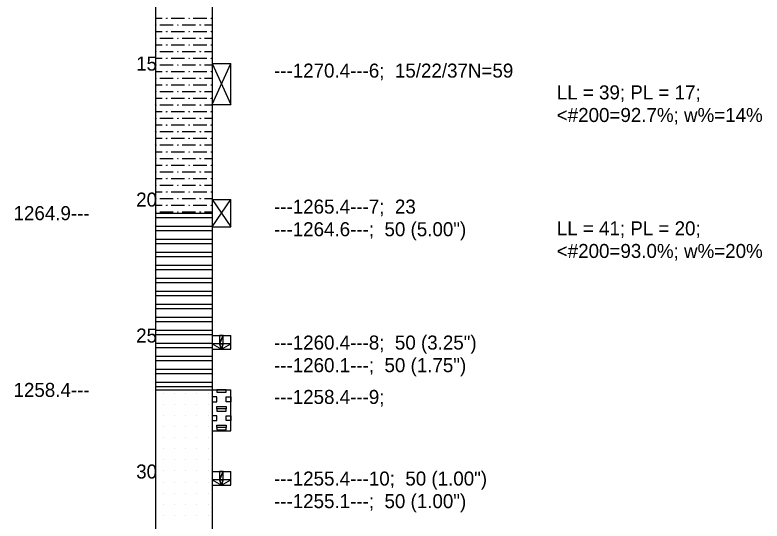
# Model space of a CAD drawing. Extents: x 2150148.6 to 2150220.1, y 143803.7 to 143875.1.
# Drawn here: x 2150175.11 to 2150181.72, y 143820.24 to 143824.71 of the extents above; entities that cross this region are included whole.
import ezdxf

# ---------------------------------------------------------------- set-up
doc = ezdxf.new("R2010")
doc.units = 0
doc.layers.add('Default', color=7, linetype='Continuous')

# ---------------------------------------------------------------- blocks, each defined once
blk = doc.blocks.new('POINT_DISPLAY')
at = {"layer": 'Default'}
blk.add_line((0, 0), (0, 0), dxfattribs=at)

msp = doc.modelspace()

# ---------------------------------------------------------------- linework, layer by layer
at = {"layer": 'Default'}
for points in [[(2150176.3564, 143827.8881), (2150176.3564, 143815.8689)], [(2150176.8564, 143827.8881), (2150176.8564, 143815.8689)], [(2150176.3564, 143824.6849), (2150176.4154, 143824.6849)], [(2150176.4548, 143824.6849), (2150176.4587, 143824.6849), (2150176.4548, 143824.681), (2150176.4548, 143824.6849)], [(2150176.4942, 143824.6849), (2150176.6123, 143824.6849)], [(2150176.6516, 143824.6849), (2150176.6556, 143824.6849), (2150176.6556, 143824.681), (2150176.6516, 143824.6849)], [(2150176.691, 143824.6849), (2150176.7501, 143824.6849)], [(2150176.7501, 143824.6849), (2150176.8091, 143824.6849)], [(2150176.8485, 143824.6849), (2150176.8524, 143824.6849), (2150176.8485, 143824.681), (2150176.8485, 143824.6849)], [(2150176.3564, 143824.6258), (2150176.3603, 143824.6258), (2150176.3603, 143824.6219), (2150176.3564, 143824.6258)], [(2150176.3957, 143824.6258), (2150176.5138, 143824.6258)], [(2150176.5532, 143824.6258), (2150176.5571, 143824.6258), (2150176.5532, 143824.6219), (2150176.5532, 143824.6258)], [(2150176.5926, 143824.6258), (2150176.7107, 143824.6258)], [(2150176.7501, 143824.6258), (2150176.754, 143824.6258), (2150176.754, 143824.6219), (2150176.7501, 143824.6258)], [(2150176.7894, 143824.6258), (2150176.8564, 143824.6258)], [(2150176.3564, 143824.5668), (2150176.4154, 143824.5668)], [(2150176.4548, 143824.5668), (2150176.4587, 143824.5668), (2150176.4548, 143824.5629), (2150176.4548, 143824.5668)], [(2150176.4942, 143824.5668), (2150176.6123, 143824.5668)], [(2150176.6516, 143824.5668), (2150176.6556, 143824.5668), (2150176.6556, 143824.5629), (2150176.6516, 143824.5668)], [(2150176.691, 143824.5668), (2150176.7501, 143824.5668)], [(2150176.7501, 143824.5668), (2150176.8091, 143824.5668)], [(2150176.8485, 143824.5668), (2150176.8524, 143824.5668), (2150176.8485, 143824.5629), (2150176.8485, 143824.5668)], [(2150176.3564, 143824.5077), (2150176.3603, 143824.5077), (2150176.3603, 143824.5038), (2150176.3564, 143824.5077)], [(2150176.3564, 143824.4487), (2150176.4154, 143824.4487)], [(2150176.3957, 143824.5077), (2150176.5138, 143824.5077)], [(2150176.4548, 143824.4487), (2150176.4587, 143824.4487), (2150176.4548, 143824.4447), (2150176.4548, 143824.4487)], [(2150176.4942, 143824.4487), (2150176.6123, 143824.4487)], [(2150176.5532, 143824.5077), (2150176.5571, 143824.5077), (2150176.5532, 143824.5038), (2150176.5532, 143824.5077)], [(2150176.5926, 143824.5077), (2150176.7107, 143824.5077)], [(2150176.6516, 143824.4487), (2150176.6556, 143824.4487), (2150176.6556, 143824.4447), (2150176.6516, 143824.4487)], [(2150176.691, 143824.4487), (2150176.7501, 143824.4487)], [(2150176.7501, 143824.5077), (2150176.754, 143824.5077), (2150176.754, 143824.5038), (2150176.7501, 143824.5077)], [(2150176.7501, 143824.4487), (2150176.8091, 143824.4487)], [(2150176.7894, 143824.5077), (2150176.8564, 143824.5077)], [(2150176.8485, 143824.4487), (2150176.8524, 143824.4487), (2150176.8485, 143824.4447), (2150176.8485, 143824.4487)], [(2150176.3564, 143824.3896), (2150176.3603, 143824.3896), (2150176.3603, 143824.3857), (2150176.3564, 143824.3896)], [(2150176.3957, 143824.3896), (2150176.5138, 143824.3896)], [(2150176.5532, 143824.3896), (2150176.5571, 143824.3896), (2150176.5532, 143824.3857), (2150176.5532, 143824.3896)], [(2150176.5926, 143824.3896), (2150176.7107, 143824.3896)], [(2150176.7501, 143824.3896), (2150176.754, 143824.3896), (2150176.754, 143824.3857), (2150176.7501, 143824.3896)], [(2150176.7894, 143824.3896), (2150176.8564, 143824.3896)], [(2150176.3564, 143824.3306), (2150176.4154, 143824.3306)], [(2150176.4548, 143824.3306), (2150176.4587, 143824.3306), (2150176.4548, 143824.3266), (2150176.4548, 143824.3306)], [(2150176.4942, 143824.3306), (2150176.6123, 143824.3306)], [(2150176.6516, 143824.3306), (2150176.6556, 143824.3306), (2150176.6556, 143824.3266), (2150176.6516, 143824.3306)], [(2150176.691, 143824.3306), (2150176.7501, 143824.3306)], [(2150176.7501, 143824.3306), (2150176.8091, 143824.3306)], [(2150176.8485, 143824.3306), (2150176.8524, 143824.3306), (2150176.8485, 143824.3266), (2150176.8485, 143824.3306)], [(2150176.3564, 143824.2715), (2150176.3603, 143824.2715), (2150176.3603, 143824.2676), (2150176.3564, 143824.2715)], [(2150176.3957, 143824.2715), (2150176.5138, 143824.2715)], [(2150176.5532, 143824.2715), (2150176.5571, 143824.2715), (2150176.5532, 143824.2676), (2150176.5532, 143824.2715)], [(2150176.5926, 143824.2715), (2150176.7107, 143824.2715)], [(2150176.7501, 143824.2715), (2150176.754, 143824.2715), (2150176.754, 143824.2676), (2150176.7501, 143824.2715)], [(2150176.7894, 143824.2715), (2150176.8564, 143824.2715)], [(2150176.8564, 143824.2823), (2150177.023, 143823.9217)], [(2150176.8564, 143823.9217), (2150177.023, 143824.2823)], [(2150176.8564, 143824.2823), (2150177.023, 143824.2823)], [(2150177.023, 143823.9217), (2150177.023, 143824.2823)], [(2150176.3564, 143824.2125), (2150176.4154, 143824.2125)], [(2150176.4548, 143824.2125), (2150176.4587, 143824.2125), (2150176.4548, 143824.2085), (2150176.4548, 143824.2125)], [(2150176.4942, 143824.2125), (2150176.6123, 143824.2125)], [(2150176.6516, 143824.2125), (2150176.6556, 143824.2125), (2150176.6556, 143824.2085), (2150176.6516, 143824.2125)], [(2150176.691, 143824.2125), (2150176.7501, 143824.2125)], [(2150176.7501, 143824.2125), (2150176.8091, 143824.2125)], [(2150176.8485, 143824.2125), (2150176.8524, 143824.2125), (2150176.8485, 143824.2085), (2150176.8485, 143824.2125)], [(2150176.3564, 143824.1534), (2150176.3603, 143824.1534), (2150176.3603, 143824.1495), (2150176.3564, 143824.1534)], [(2150176.3957, 143824.1534), (2150176.5138, 143824.1534)], [(2150176.5532, 143824.1534), (2150176.5571, 143824.1534), (2150176.5532, 143824.1495), (2150176.5532, 143824.1534)], [(2150176.5926, 143824.1534), (2150176.7107, 143824.1534)], [(2150176.7501, 143824.1534), (2150176.754, 143824.1534), (2150176.754, 143824.1495), (2150176.7501, 143824.1534)], [(2150176.7894, 143824.1534), (2150176.8564, 143824.1534)], [(2150176.3564, 143824.0944), (2150176.4154, 143824.0944)], [(2150176.4548, 143824.0944), (2150176.4587, 143824.0944), (2150176.4548, 143824.0904), (2150176.4548, 143824.0944)], [(2150176.4942, 143824.0944), (2150176.6123, 143824.0944)], [(2150176.6516, 143824.0944), (2150176.6556, 143824.0944), (2150176.6556, 143824.0904), (2150176.6516, 143824.0944)], [(2150176.691, 143824.0944), (2150176.7501, 143824.0944)], [(2150176.7501, 143824.0944), (2150176.8091, 143824.0944)], [(2150176.8485, 143824.0944), (2150176.8524, 143824.0944), (2150176.8485, 143824.0904), (2150176.8485, 143824.0944)], [(2150176.3564, 143824.0353), (2150176.3603, 143824.0353), (2150176.3603, 143824.0314), (2150176.3564, 143824.0353)], [(2150176.3957, 143824.0353), (2150176.5138, 143824.0353)], [(2150176.5532, 143824.0353), (2150176.5571, 143824.0353), (2150176.5532, 143824.0314), (2150176.5532, 143824.0353)], [(2150176.5926, 143824.0353), (2150176.7107, 143824.0353)], [(2150176.7501, 143824.0353), (2150176.754, 143824.0353), (2150176.754, 143824.0314), (2150176.7501, 143824.0353)], [(2150176.7894, 143824.0353), (2150176.8564, 143824.0353)], [(2150176.3564, 143823.9762), (2150176.4154, 143823.9762)], [(2150176.4548, 143823.9762), (2150176.4587, 143823.9762), (2150176.4548, 143823.9723), (2150176.4548, 143823.9762)], [(2150176.4942, 143823.9762), (2150176.6123, 143823.9762)], [(2150176.6516, 143823.9762), (2150176.6556, 143823.9762), (2150176.6556, 143823.9723), (2150176.6516, 143823.9762)], [(2150176.691, 143823.9762), (2150176.7501, 143823.9762)], [(2150176.7501, 143823.9762), (2150176.8091, 143823.9762)], [(2150176.8485, 143823.9762), (2150176.8524, 143823.9762), (2150176.8485, 143823.9723), (2150176.8485, 143823.9762)], [(2150176.8564, 143823.9217), (2150177.023, 143823.9217)], [(2150176.3564, 143823.9172), (2150176.3603, 143823.9172), (2150176.3603, 143823.9133), (2150176.3564, 143823.9172)], [(2150176.3564, 143823.8581), (2150176.4154, 143823.8581)], [(2150176.3957, 143823.9172), (2150176.5138, 143823.9172)], [(2150176.4548, 143823.8581), (2150176.4587, 143823.8581), (2150176.4548, 143823.8542), (2150176.4548, 143823.8581)], [(2150176.4942, 143823.8581), (2150176.6123, 143823.8581)], [(2150176.5532, 143823.9172), (2150176.5571, 143823.9172), (2150176.5532, 143823.9133), (2150176.5532, 143823.9172)], [(2150176.5926, 143823.9172), (2150176.7107, 143823.9172)], [(2150176.6516, 143823.8581), (2150176.6556, 143823.8581), (2150176.6556, 143823.8542), (2150176.6516, 143823.8581)], [(2150176.691, 143823.8581), (2150176.7501, 143823.8581)], [(2150176.7501, 143823.9172), (2150176.754, 143823.9172), (2150176.754, 143823.9133), (2150176.7501, 143823.9172)], [(2150176.7501, 143823.8581), (2150176.8091, 143823.8581)], [(2150176.7894, 143823.9172), (2150176.8564, 143823.9172)], [(2150176.8485, 143823.8581), (2150176.8524, 143823.8581), (2150176.8485, 143823.8542), (2150176.8485, 143823.8581)], [(2150176.3564, 143823.7991), (2150176.3603, 143823.7991), (2150176.3603, 143823.7951), (2150176.3564, 143823.7991)], [(2150176.3957, 143823.7991), (2150176.5138, 143823.7991)], [(2150176.5532, 143823.7991), (2150176.5571, 143823.7991), (2150176.5532, 143823.7951), (2150176.5532, 143823.7991)], [(2150176.5926, 143823.7991), (2150176.7107, 143823.7991)], [(2150176.7501, 143823.7991), (2150176.754, 143823.7991), (2150176.754, 143823.7951), (2150176.7501, 143823.7991)], [(2150176.7894, 143823.7991), (2150176.8564, 143823.7991)], [(2150176.3564, 143823.74), (2150176.4154, 143823.74)], [(2150176.4548, 143823.74), (2150176.4587, 143823.74), (2150176.4548, 143823.7361), (2150176.4548, 143823.74)], [(2150176.4942, 143823.74), (2150176.6123, 143823.74)], [(2150176.6516, 143823.74), (2150176.6556, 143823.74), (2150176.6556, 143823.7361), (2150176.6516, 143823.74)], [(2150176.691, 143823.74), (2150176.7501, 143823.74)], [(2150176.7501, 143823.74), (2150176.8091, 143823.74)], [(2150176.8485, 143823.74), (2150176.8524, 143823.74), (2150176.8485, 143823.7361), (2150176.8485, 143823.74)], [(2150176.3564, 143823.681), (2150176.3603, 143823.681), (2150176.3603, 143823.677), (2150176.3564, 143823.681)], [(2150176.3957, 143823.681), (2150176.5138, 143823.681)], [(2150176.5532, 143823.681), (2150176.5571, 143823.681), (2150176.5532, 143823.677), (2150176.5532, 143823.681)], [(2150176.5926, 143823.681), (2150176.7107, 143823.681)], [(2150176.7501, 143823.681), (2150176.754, 143823.681), (2150176.754, 143823.677), (2150176.7501, 143823.681)], [(2150176.7894, 143823.681), (2150176.8564, 143823.681)], [(2150176.3564, 143823.6219), (2150176.4154, 143823.6219)], [(2150176.4548, 143823.6219), (2150176.4587, 143823.6219), (2150176.4548, 143823.618), (2150176.4548, 143823.6219)], [(2150176.4942, 143823.6219), (2150176.6123, 143823.6219)], [(2150176.6516, 143823.6219), (2150176.6556, 143823.6219), (2150176.6556, 143823.618), (2150176.6516, 143823.6219)], [(2150176.691, 143823.6219), (2150176.7501, 143823.6219)], [(2150176.7501, 143823.6219), (2150176.8091, 143823.6219)], [(2150176.8485, 143823.6219), (2150176.8524, 143823.6219), (2150176.8485, 143823.618), (2150176.8485, 143823.6219)], [(2150176.3564, 143823.5629), (2150176.3603, 143823.5629), (2150176.3603, 143823.5589), (2150176.3564, 143823.5629)], [(2150176.3957, 143823.5629), (2150176.5138, 143823.5629)], [(2150176.5532, 143823.5629), (2150176.5571, 143823.5629), (2150176.5532, 143823.5589), (2150176.5532, 143823.5629)], [(2150176.5926, 143823.5629), (2150176.7107, 143823.5629)], [(2150176.7501, 143823.5629), (2150176.754, 143823.5629), (2150176.754, 143823.5589), (2150176.7501, 143823.5629)], [(2150176.7894, 143823.5629), (2150176.8564, 143823.5629)], [(2150176.3564, 143823.5038), (2150176.4154, 143823.5038)], [(2150176.4548, 143823.5038), (2150176.4587, 143823.5038), (2150176.4548, 143823.4999), (2150176.4548, 143823.5038)], [(2150176.4942, 143823.5038), (2150176.6123, 143823.5038)], [(2150176.6516, 143823.5038), (2150176.6556, 143823.5038), (2150176.6556, 143823.4999), (2150176.6516, 143823.5038)], [(2150176.691, 143823.5038), (2150176.7501, 143823.5038)], [(2150176.7501, 143823.5038), (2150176.8091, 143823.5038)], [(2150176.8485, 143823.5038), (2150176.8524, 143823.5038), (2150176.8485, 143823.4999), (2150176.8485, 143823.5038)], [(2150176.3564, 143823.4447), (2150176.3603, 143823.4447), (2150176.3603, 143823.4408), (2150176.3564, 143823.4447)], [(2150176.3957, 143823.4447), (2150176.5138, 143823.4447)], [(2150176.5532, 143823.4447), (2150176.5571, 143823.4447), (2150176.5532, 143823.4408), (2150176.5532, 143823.4447)], [(2150176.5926, 143823.4447), (2150176.7107, 143823.4447)], [(2150176.7501, 143823.4447), (2150176.754, 143823.4447), (2150176.754, 143823.4408), (2150176.7501, 143823.4447)], [(2150176.7894, 143823.4447), (2150176.8564, 143823.4447)], [(2150176.3564, 143823.3857), (2150176.4154, 143823.3857)], [(2150176.3564, 143823.3266), (2150176.3603, 143823.3266), (2150176.3603, 143823.3227), (2150176.3564, 143823.3266)], [(2150176.3957, 143823.3266), (2150176.5138, 143823.3266)], [(2150176.4548, 143823.3857), (2150176.4587, 143823.3857), (2150176.4548, 143823.3818), (2150176.4548, 143823.3857)], [(2150176.4942, 143823.3857), (2150176.6123, 143823.3857)], [(2150176.5532, 143823.3266), (2150176.5571, 143823.3266), (2150176.5532, 143823.3227), (2150176.5532, 143823.3266)], [(2150176.5926, 143823.3266), (2150176.7107, 143823.3266)], [(2150176.6516, 143823.3857), (2150176.6556, 143823.3857), (2150176.6556, 143823.3818), (2150176.6516, 143823.3857)], [(2150176.691, 143823.3857), (2150176.7501, 143823.3857)], [(2150176.7501, 143823.3857), (2150176.8091, 143823.3857)], [(2150176.7501, 143823.3266), (2150176.754, 143823.3266), (2150176.754, 143823.3227), (2150176.7501, 143823.3266)], [(2150176.7894, 143823.3266), (2150176.8564, 143823.3266)], [(2150176.8485, 143823.3857), (2150176.8524, 143823.3857), (2150176.8485, 143823.3818), (2150176.8485, 143823.3857)], [(2150176.3564, 143823.2676), (2150176.4154, 143823.2676)], [(2150176.4548, 143823.2676), (2150176.4587, 143823.2676), (2150176.4548, 143823.2636), (2150176.4548, 143823.2676)], [(2150176.4942, 143823.2676), (2150176.6123, 143823.2676)], [(2150176.6516, 143823.2676), (2150176.6556, 143823.2676), (2150176.6556, 143823.2636), (2150176.6516, 143823.2676)], [(2150176.691, 143823.2676), (2150176.7501, 143823.2676)], [(2150176.7501, 143823.2676), (2150176.8091, 143823.2676)], [(2150176.8485, 143823.2676), (2150176.8524, 143823.2676), (2150176.8485, 143823.2636), (2150176.8485, 143823.2676)], [(2150176.3564, 143823.2085), (2150176.3603, 143823.2085), (2150176.3603, 143823.2046), (2150176.3564, 143823.2085)], [(2150176.3957, 143823.2085), (2150176.5138, 143823.2085)], [(2150176.5532, 143823.2085), (2150176.5571, 143823.2085), (2150176.5532, 143823.2046), (2150176.5532, 143823.2085)], [(2150176.5926, 143823.2085), (2150176.7107, 143823.2085)], [(2150176.7501, 143823.2085), (2150176.754, 143823.2085), (2150176.754, 143823.2046), (2150176.7501, 143823.2085)], [(2150176.7894, 143823.2085), (2150176.8564, 143823.2085)], [(2150176.3564, 143823.1495), (2150176.4154, 143823.1495)], [(2150176.4548, 143823.1495), (2150176.4587, 143823.1495), (2150176.4548, 143823.1455), (2150176.4548, 143823.1495)], [(2150176.4942, 143823.1495), (2150176.6123, 143823.1495)], [(2150176.6516, 143823.1495), (2150176.6556, 143823.1495), (2150176.6556, 143823.1455), (2150176.6516, 143823.1495)], [(2150176.691, 143823.1495), (2150176.7501, 143823.1495)], [(2150176.7501, 143823.1495), (2150176.8091, 143823.1495)], [(2150176.8485, 143823.1495), (2150176.8524, 143823.1495), (2150176.8485, 143823.1455), (2150176.8485, 143823.1495)], [(2150176.3564, 143823.0904), (2150176.3603, 143823.0904), (2150176.3603, 143823.0865), (2150176.3564, 143823.0904)], [(2150176.3957, 143823.0904), (2150176.5138, 143823.0904)], [(2150176.5532, 143823.0904), (2150176.5571, 143823.0904), (2150176.5532, 143823.0865), (2150176.5532, 143823.0904)], [(2150176.5926, 143823.0904), (2150176.7107, 143823.0904)], [(2150176.7501, 143823.0904), (2150176.754, 143823.0904), (2150176.754, 143823.0865), (2150176.7501, 143823.0904)], [(2150176.7894, 143823.0904), (2150176.8564, 143823.0904)], [(2150176.8564, 143823.0804), (2150177.023, 143822.84)], [(2150176.8564, 143822.84), (2150177.023, 143823.0804)], [(2150176.8564, 143823.0804), (2150177.023, 143823.0804)], [(2150177.023, 143822.84), (2150177.023, 143823.0804)], [(2150176.3564, 143823.0314), (2150176.4154, 143823.0314)], [(2150176.4548, 143823.0314), (2150176.4587, 143823.0314), (2150176.4548, 143823.0274), (2150176.4548, 143823.0314)], [(2150176.4942, 143823.0314), (2150176.6123, 143823.0314)], [(2150176.6516, 143823.0314), (2150176.6556, 143823.0314), (2150176.6556, 143823.0274), (2150176.6516, 143823.0314)], [(2150176.691, 143823.0314), (2150176.7501, 143823.0314)], [(2150176.7501, 143823.0314), (2150176.8091, 143823.0314)], [(2150176.8485, 143823.0314), (2150176.8524, 143823.0314), (2150176.8485, 143823.0274), (2150176.8485, 143823.0314)], [(2150176.3564, 143822.9723), (2150176.3603, 143822.9723), (2150176.3603, 143822.9684), (2150176.3564, 143822.9723)], [(2150176.3564, 143822.9602), (2150176.8564, 143822.9602)], [(2150176.3564, 143822.9602), (2150176.8564, 143822.9602)], [(2150176.3957, 143822.9723), (2150176.5138, 143822.9723)], [(2150176.5532, 143822.9723), (2150176.5571, 143822.9723), (2150176.5532, 143822.9684), (2150176.5532, 143822.9723)], [(2150176.5926, 143822.9723), (2150176.7107, 143822.9723)], [(2150176.7501, 143822.9723), (2150176.754, 143822.9723), (2150176.754, 143822.9684), (2150176.7501, 143822.9723)], [(2150176.7894, 143822.9723), (2150176.8564, 143822.9723)], [(2150176.3564, 143822.9208), (2150176.8564, 143822.9208)], [(2150176.3564, 143822.8454), (2150176.8564, 143822.8454)], [(2150176.3564, 143822.806), (2150176.8564, 143822.806)], [(2150176.8564, 143822.84), (2150177.023, 143822.84)], [(2150176.3564, 143822.7305), (2150176.8564, 143822.7305)], [(2150176.3564, 143822.6912), (2150176.8564, 143822.6912)], [(2150176.3564, 143822.6157), (2150176.8564, 143822.6157)], [(2150176.3564, 143822.5763), (2150176.8564, 143822.5763)], [(2150176.3564, 143822.5009), (2150176.8564, 143822.5009)], [(2150176.3564, 143822.4615), (2150176.8564, 143822.4615)], [(2150176.3564, 143822.386), (2150176.8564, 143822.386)], [(2150176.3564, 143822.3467), (2150176.8564, 143822.3467)], [(2150176.3564, 143822.2712), (2150176.8564, 143822.2712)], [(2150176.3564, 143822.2319), (2150176.8564, 143822.2319)], [(2150176.3564, 143822.1564), (2150176.8564, 143822.1564)], [(2150176.3564, 143822.117), (2150176.8564, 143822.117)], [(2150176.3564, 143822.0416), (2150176.8564, 143822.0416)], [(2150176.3564, 143822.0022), (2150176.8564, 143822.0022)], [(2150176.3564, 143821.9267), (2150176.8564, 143821.9267)], [(2150176.3564, 143821.8874), (2150176.8564, 143821.8874)], [(2150176.8564, 143821.8785), (2150177.023, 143821.8785)], [(2150177.023, 143821.7583), (2150177.023, 143821.8785)], [(2150176.3564, 143821.8119), (2150176.8564, 143821.8119)], [(2150176.3564, 143821.7725), (2150176.8564, 143821.7725)], [(2150176.8564, 143821.7583), (2150177.023, 143821.7583)], [(2150176.3564, 143821.6971), (2150176.8564, 143821.6971)], [(2150176.3564, 143821.6577), (2150176.8564, 143821.6577)], [(2150176.3564, 143821.5822), (2150176.8564, 143821.5822)], [(2150176.3564, 143821.5429), (2150176.8564, 143821.5429)], [(2150176.3564, 143821.4674), (2150176.8564, 143821.4674)], [(2150176.3564, 143821.428), (2150176.8564, 143821.428)], [(2150176.3564, 143821.3977), (2150176.8564, 143821.3977)], [(2150176.8564, 143821.3977), (2150177.023, 143821.3977)], [(2150177.023, 143821.0371), (2150177.023, 143821.3977)], [(2150176.8564, 143821.0371), (2150177.023, 143821.0371)], [(2150176.8564, 143820.6765), (2150177.023, 143820.6765)], [(2150177.023, 143820.5564), (2150177.023, 143820.6765)], [(2150176.8564, 143820.5564), (2150177.023, 143820.5564)]]:
    msp.add_lwpolyline(points, dxfattribs=at)
for points in [[(2150176.923, 143821.8064), (2150176.9564, 143821.8064), (2150176.9564, 143821.8785), (2150176.923, 143821.8064)], [(2150176.923, 143821.8064), (2150176.9564, 143821.8785), (2150176.923, 143821.8785), (2150176.923, 143821.8064)], [(2150176.923, 143821.8064), (2150176.8564, 143821.8064), (2150176.9397, 143821.7583), (2150176.923, 143821.8064)], [(2150176.923, 143821.8064), (2150176.9397, 143821.7583), (2150176.9564, 143821.8064), (2150176.923, 143821.8064)], [(2150176.9397, 143821.7583), (2150177.023, 143821.8064), (2150176.9564, 143821.8064), (2150176.9397, 143821.7583)], [(2150176.898, 143821.3977), (2150176.898, 143821.3769), (2150176.9814, 143821.3769), (2150176.9814, 143821.3977)], [(2150176.8564, 143821.2935), (2150176.898, 143821.2935), (2150176.898, 143821.3352), (2150176.8564, 143821.3352)], [(2150177.023, 143821.2935), (2150176.9814, 143821.2935), (2150176.9814, 143821.3352), (2150177.023, 143821.3352)], [(2150176.898, 143821.231), (2150176.898, 143821.2519), (2150176.9814, 143821.2519), (2150176.9814, 143821.231)], [(2150176.898, 143821.231), (2150176.898, 143821.2102), (2150176.9814, 143821.2102), (2150176.9814, 143821.231)], [(2150176.8564, 143821.1269), (2150176.898, 143821.1269), (2150176.898, 143821.1685), (2150176.8564, 143821.1685)], [(2150177.023, 143821.1269), (2150176.9814, 143821.1269), (2150176.9814, 143821.1685), (2150177.023, 143821.1685)], [(2150176.898, 143821.0644), (2150176.898, 143821.0852), (2150176.9814, 143821.0852), (2150176.9814, 143821.0644)], [(2150176.898, 143821.0644), (2150176.898, 143821.0435), (2150176.9814, 143821.0435), (2150176.9814, 143821.0644)], [(2150176.923, 143820.6044), (2150176.9564, 143820.6044), (2150176.9564, 143820.6765), (2150176.923, 143820.6044)], [(2150176.923, 143820.6044), (2150176.9564, 143820.6765), (2150176.923, 143820.6765), (2150176.923, 143820.6044)], [(2150176.923, 143820.6044), (2150176.8564, 143820.6044), (2150176.9397, 143820.5564), (2150176.923, 143820.6044)], [(2150176.923, 143820.6044), (2150176.9397, 143820.5564), (2150176.9564, 143820.6044), (2150176.923, 143820.6044)], [(2150176.9397, 143820.5564), (2150177.023, 143820.6044), (2150176.9564, 143820.6044), (2150176.9397, 143820.5564)]]:
    msp.add_lwpolyline(points, close=True, dxfattribs=at)

# ---------------------------------------------------------------- block references
at = {"layer": 'Default', "xscale": 0.39369999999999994, "yscale": 0.3936999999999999}
for p in [(2150176.4275, 143821.3704), (2150176.5259, 143821.3704), (2150176.6244, 143821.3704), (2150176.7228, 143821.3704), (2150176.8212, 143821.3704), (2150176.4275, 143821.272), (2150176.5259, 143821.272), (2150176.6244, 143821.272), (2150176.7228, 143821.272), (2150176.8212, 143821.272), (2150176.4275, 143821.1736), (2150176.5259, 143821.1736), (2150176.6244, 143821.1736), (2150176.7228, 143821.1736), (2150176.8212, 143821.1736), (2150176.4275, 143821.0752), (2150176.5259, 143821.0752), (2150176.6244, 143821.0752), (2150176.7228, 143821.0752), (2150176.8212, 143821.0752), (2150176.4275, 143820.9767), (2150176.5259, 143820.9767), (2150176.6244, 143820.9767), (2150176.7228, 143820.9767), (2150176.8212, 143820.9767), (2150176.4275, 143820.8783), (2150176.5259, 143820.8783), (2150176.6244, 143820.8783), (2150176.7228, 143820.8783), (2150176.8212, 143820.8783), (2150176.4275, 143820.7799), (2150176.5259, 143820.7799), (2150176.6244, 143820.7799), (2150176.7228, 143820.7799), (2150176.8212, 143820.7799), (2150176.4275, 143820.6815), (2150176.5259, 143820.6815), (2150176.6244, 143820.6815), (2150176.7228, 143820.6815), (2150176.8212, 143820.6815), (2150176.4275, 143820.583), (2150176.5259, 143820.583), (2150176.6244, 143820.583), (2150176.7228, 143820.583), (2150176.8212, 143820.583), (2150176.4275, 143820.4846), (2150176.5259, 143820.4846), (2150176.6244, 143820.4846), (2150176.7228, 143820.4846), (2150176.8212, 143820.4846), (2150176.4275, 143820.3862), (2150176.5259, 143820.3862), (2150176.6244, 143820.3862), (2150176.7228, 143820.3862), (2150176.8212, 143820.3862), (2150176.4275, 143820.2878), (2150176.5259, 143820.2878), (2150176.6244, 143820.2878), (2150176.7228, 143820.2878), (2150176.8212, 143820.2878)]:
    msp.add_blockref('POINT_DISPLAY', p, dxfattribs=at)

# ---------------------------------------------------------------- texts
at = {"layer": 'Default'}
for s, p in [('15', (2150176.1859, 143824.2203)), ('---1270.4---6;  15/22/37N=59', (2150177.4044, 143824.1583)), ('LL = 39; PL = 17;', (2150179.9044, 143823.966)), ('<#200=92.7%; w%=14%', (2150179.9044, 143823.766)), ('20', (2150176.1859, 143823.0184)), ('---1265.4---7;  23', (2150177.4044, 143822.9564)), ('1264.9---', (2150175.1015, 143822.8982)), ('---1264.6---;  50 (5.00")', (2150177.4044, 143822.7564)), ('LL = 41; PL = 20;', (2150179.9044, 143822.7641)), ('<#200=93.0%; w%=20%', (2150179.9044, 143822.5641)), ('25', (2150176.1859, 143821.8165)), ('---1260.4---8;  50 (3.25")', (2150177.4044, 143821.7545)), ('---1260.1---;  50 (1.75")', (2150177.4044, 143821.5545)), ('1258.4---', (2150175.1015, 143821.3357)), ('---1258.4---9;', (2150177.4044, 143821.2737)), ('30', (2150176.1859, 143820.6145)), ('---1255.4---10;  50 (1.00")', (2150177.4044, 143820.5525)), ('---1255.1---;  50 (1.00")', (2150177.4044, 143820.3525))]:
    msp.add_text(s, height=0.124, dxfattribs=at).set_placement(p)

doc.saveas('drawing.dxf')
